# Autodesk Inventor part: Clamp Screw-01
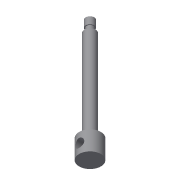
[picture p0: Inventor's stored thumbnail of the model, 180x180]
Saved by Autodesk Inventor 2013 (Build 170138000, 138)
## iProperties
Created: 2002-02
Part Number: Clamp Screw-01
Material: Generic
Document SubType Name: Modeling
Designer: ***
Density: 1 g/cm^3
Author: ***
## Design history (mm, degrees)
derived "Clamp Screw.ipt"
feature "Solid1::Clamp Screw.ipt"
tag "TaggingFeature1"
body "Solid1"
other parameters: "d1" = 8, "d2" = 13, "d3" = 8, "d4" = 25, "d5" = 3, "d6" = 8, "d7" = 13, "d8" = 22, "d10" = 102, "d14" = 11, "d16" = 0
